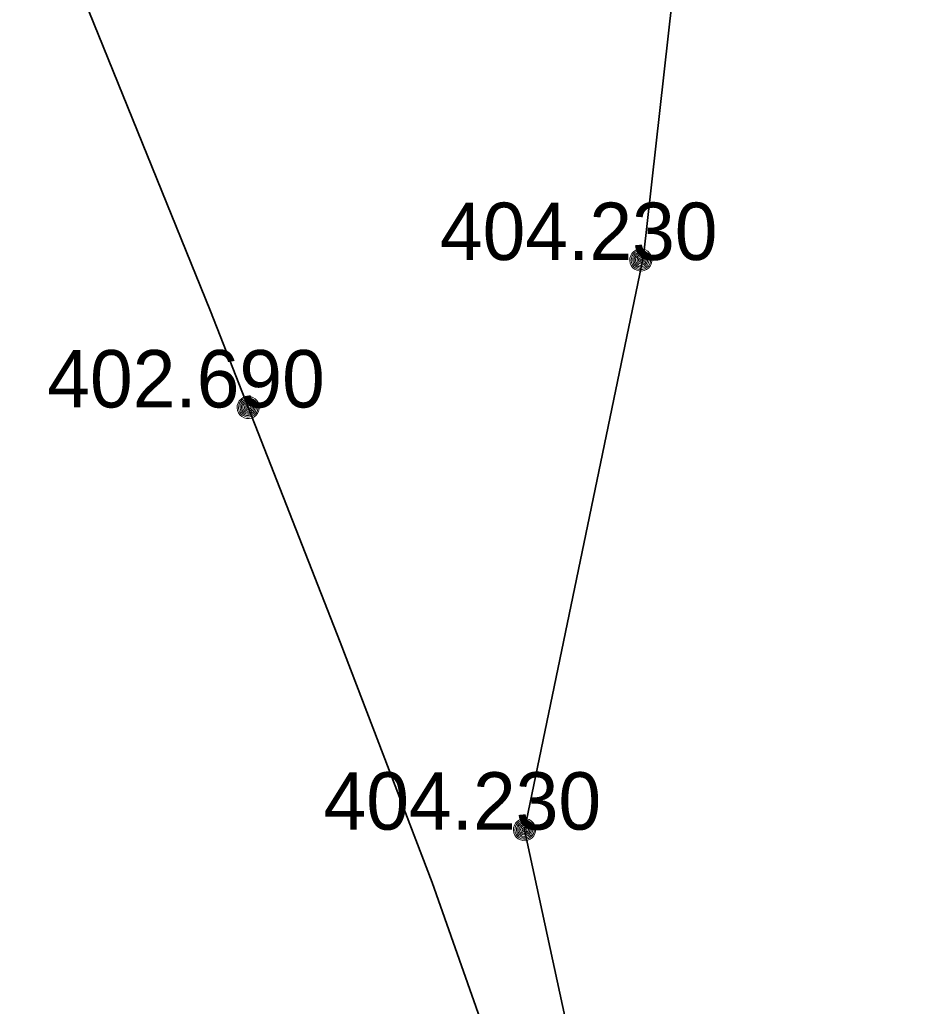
# Model space of a CAD drawing. Extents: x -873619 to -867639, y -1015082 to -1012326.
# Drawn here: x -867993.66 to -867974.61, y -1012778.89 to -1012758.26 of the extents above; entities that cross this region are included whole.
import ezdxf

# ---------------------------------------------------------------- set-up
doc = ezdxf.new("R2010")
doc.units = 0
doc.header["$LTSCALE"] = 0.44
doc.layers.add('1', color=7, linetype='Continuous', lineweight=13)
doc.layers.add('21', color=7, linetype='Continuous', lineweight=35)

msp = doc.modelspace()

# ---------------------------------------------------------------- linework, layer by layer
at = {"layer": '1', "lineweight": 35}
msp.add_lwpolyline([(-867974.611, -1012725.697), (-867976.949, -1012730.385), (-867980.624, -1012763.205), (-867983.112, -1012775.195), (-867978.719, -1012795.525), (-867979.823, -1012805.464), (-867997.768, -1012829.005), (-868011.042, -1012836.499), (-868058.95, -1012844.4), (-868077.43, -1012833.46), (-868085.171, -1012827.86)], dxfattribs=at)
at = {"layer": '1'}
for points in [[(-867980.449, -1012763.287), (-867980.455, -1012763.235), (-867980.472, -1012763.185), (-867980.501, -1012763.141), (-867980.538, -1012763.104), (-867980.583, -1012763.077), (-867980.633, -1012763.06), (-867980.686, -1012763.056), (-867980.738, -1012763.063), (-867980.787, -1012763.082), (-867980.83, -1012763.111), (-867980.866, -1012763.15), (-867980.892, -1012763.195), (-867980.908, -1012763.246), (-867980.911, -1012763.298), (-867980.903, -1012763.35), (-867980.883, -1012763.399), (-867980.852, -1012763.442), (-867980.813, -1012763.476), (-867980.767, -1012763.502), (-867980.716, -1012763.516), (-867980.663, -1012763.518), (-867980.612, -1012763.508), (-867980.564, -1012763.487), (-867980.521, -1012763.456), (-867980.487, -1012763.415), (-867980.463, -1012763.369), (-867980.451, -1012763.318)], [(-867980.479, -1012763.287), (-867980.485, -1012763.238), (-867980.502, -1012763.192), (-867980.53, -1012763.152), (-867980.567, -1012763.12), (-867980.611, -1012763.098), (-867980.659, -1012763.087), (-867980.708, -1012763.087), (-867980.755, -1012763.1), (-867980.798, -1012763.124), (-867980.834, -1012763.157), (-867980.861, -1012763.198), (-867980.877, -1012763.245), (-867980.881, -1012763.294), (-867980.874, -1012763.342), (-867980.855, -1012763.387), (-867980.825, -1012763.427), (-867980.787, -1012763.458), (-867980.743, -1012763.478), (-867980.695, -1012763.488), (-867980.646, -1012763.486), (-867980.599, -1012763.471), (-867980.556, -1012763.446), (-867980.522, -1012763.412), (-867980.496, -1012763.37), (-867980.482, -1012763.323)], [(-867980.509, -1012763.287), (-867980.515, -1012763.242), (-867980.532, -1012763.2), (-867980.56, -1012763.165), (-867980.596, -1012763.138), (-867980.638, -1012763.121), (-867980.683, -1012763.116), (-867980.728, -1012763.122), (-867980.769, -1012763.141), (-867980.804, -1012763.169), (-867980.831, -1012763.206), (-867980.847, -1012763.248), (-867980.851, -1012763.293), (-867980.844, -1012763.338), (-867980.825, -1012763.379), (-867980.796, -1012763.413), (-867980.759, -1012763.439), (-867980.716, -1012763.455), (-867980.671, -1012763.458), (-867980.626, -1012763.45), (-867980.586, -1012763.43), (-867980.552, -1012763.401), (-867980.526, -1012763.363), (-867980.512, -1012763.32)], [(-867980.539, -1012763.287), (-867980.544, -1012763.246), (-867980.562, -1012763.209), (-867980.589, -1012763.178), (-867980.624, -1012763.157), (-867980.664, -1012763.146), (-867980.705, -1012763.148), (-867980.744, -1012763.161), (-867980.778, -1012763.185), (-867980.803, -1012763.217), (-867980.818, -1012763.255), (-867980.821, -1012763.296), (-867980.813, -1012763.336), (-867980.793, -1012763.372), (-867980.764, -1012763.401), (-867980.727, -1012763.42), (-867980.687, -1012763.428), (-867980.646, -1012763.424), (-867980.608, -1012763.409), (-867980.576, -1012763.383), (-867980.553, -1012763.349), (-867980.54, -1012763.31)], [(-867980.569, -1012763.287), (-867980.574, -1012763.251), (-867980.592, -1012763.219), (-867980.618, -1012763.194), (-867980.652, -1012763.179), (-867980.688, -1012763.176), (-867980.723, -1012763.184), (-867980.754, -1012763.204), (-867980.777, -1012763.232), (-867980.79, -1012763.266), (-867980.79, -1012763.303), (-867980.779, -1012763.338), (-867980.758, -1012763.367), (-867980.728, -1012763.388), (-867980.693, -1012763.398), (-867980.656, -1012763.396), (-867980.622, -1012763.382), (-867980.595, -1012763.359), (-867980.576, -1012763.327), (-867980.569, -1012763.292)], [(-867980.599, -1012763.287), (-867980.604, -1012763.256), (-867980.621, -1012763.23), (-867980.647, -1012763.213), (-867980.677, -1012763.206), (-867980.708, -1012763.21), (-867980.735, -1012763.227), (-867980.753, -1012763.251), (-867980.761, -1012763.282), (-867980.757, -1012763.312), (-867980.742, -1012763.34), (-867980.718, -1012763.359), (-867980.688, -1012763.368), (-867980.657, -1012763.365), (-867980.629, -1012763.351), (-867980.609, -1012763.327), (-867980.599, -1012763.298)], [(-867980.629, -1012763.287), (-867980.634, -1012763.263), (-867980.651, -1012763.245), (-867980.674, -1012763.236), (-867980.698, -1012763.239), (-867980.719, -1012763.253), (-867980.73, -1012763.275), (-867980.73, -1012763.3), (-867980.718, -1012763.321), (-867980.698, -1012763.335), (-867980.673, -1012763.338), (-867980.65, -1012763.329), (-867980.634, -1012763.311)], [(-867980.659, -1012763.287), (-867980.664, -1012763.272), (-867980.679, -1012763.266), (-867980.694, -1012763.27), (-867980.701, -1012763.284), (-867980.697, -1012763.299), (-867980.684, -1012763.308), (-867980.669, -1012763.305), (-867980.659, -1012763.293)], [(-867988.656, -1012766.369), (-867988.662, -1012766.317), (-867988.679, -1012766.267), (-867988.708, -1012766.223), (-867988.745, -1012766.186), (-867988.79, -1012766.159), (-867988.84, -1012766.142), (-867988.893, -1012766.138), (-867988.945, -1012766.145), (-867988.994, -1012766.164), (-867989.037, -1012766.193), (-867989.073, -1012766.232), (-867989.099, -1012766.277), (-867989.115, -1012766.328), (-867989.118, -1012766.38), (-867989.11, -1012766.432), (-867989.09, -1012766.481), (-867989.059, -1012766.524), (-867989.02, -1012766.558), (-867988.974, -1012766.584), (-867988.923, -1012766.598), (-867988.87, -1012766.6), (-867988.819, -1012766.59), (-867988.771, -1012766.569), (-867988.728, -1012766.538), (-867988.694, -1012766.497), (-867988.67, -1012766.451), (-867988.657, -1012766.4)], [(-867988.686, -1012766.369), (-867988.692, -1012766.32), (-867988.709, -1012766.274), (-867988.737, -1012766.234), (-867988.774, -1012766.202), (-867988.818, -1012766.18), (-867988.866, -1012766.169), (-867988.915, -1012766.169), (-867988.962, -1012766.182), (-867989.005, -1012766.206), (-867989.041, -1012766.239), (-867989.068, -1012766.28), (-867989.084, -1012766.327), (-867989.088, -1012766.376), (-867989.081, -1012766.424), (-867989.062, -1012766.469), (-867989.032, -1012766.509), (-867988.994, -1012766.54), (-867988.95, -1012766.56), (-867988.902, -1012766.57), (-867988.853, -1012766.568), (-867988.806, -1012766.553), (-867988.763, -1012766.528), (-867988.728, -1012766.494), (-867988.703, -1012766.452), (-867988.689, -1012766.405)], [(-867988.716, -1012766.369), (-867988.722, -1012766.324), (-867988.739, -1012766.282), (-867988.767, -1012766.247), (-867988.803, -1012766.22), (-867988.845, -1012766.203), (-867988.89, -1012766.198), (-867988.934, -1012766.204), (-867988.976, -1012766.223), (-867989.011, -1012766.251), (-867989.038, -1012766.288), (-867989.054, -1012766.33), (-867989.058, -1012766.375), (-867989.051, -1012766.42), (-867989.032, -1012766.461), (-867989.003, -1012766.495), (-867988.966, -1012766.521), (-867988.923, -1012766.537), (-867988.878, -1012766.54), (-867988.833, -1012766.532), (-867988.793, -1012766.512), (-867988.759, -1012766.483), (-867988.733, -1012766.445), (-867988.719, -1012766.402)], [(-867988.746, -1012766.369), (-867988.75, -1012766.328), (-867988.769, -1012766.291), (-867988.796, -1012766.26), (-867988.831, -1012766.239), (-867988.871, -1012766.228), (-867988.912, -1012766.23), (-867988.951, -1012766.243), (-867988.985, -1012766.267), (-867989.01, -1012766.299), (-867989.025, -1012766.337), (-867989.027, -1012766.378), (-867989.02, -1012766.418), (-867989, -1012766.454), (-867988.971, -1012766.483), (-867988.934, -1012766.502), (-867988.894, -1012766.51), (-867988.853, -1012766.506), (-867988.815, -1012766.491), (-867988.782, -1012766.465), (-867988.76, -1012766.431), (-867988.747, -1012766.392)], [(-867988.776, -1012766.369), (-867988.781, -1012766.333), (-867988.799, -1012766.301), (-867988.825, -1012766.276), (-867988.858, -1012766.261), (-867988.895, -1012766.258), (-867988.929, -1012766.266), (-867988.961, -1012766.286), (-867988.983, -1012766.314), (-867988.997, -1012766.348), (-867988.997, -1012766.385), (-867988.986, -1012766.42), (-867988.965, -1012766.449), (-867988.934, -1012766.47), (-867988.9, -1012766.48), (-867988.863, -1012766.478), (-867988.829, -1012766.464), (-867988.802, -1012766.441), (-867988.782, -1012766.409), (-867988.776, -1012766.374)], [(-867988.806, -1012766.369), (-867988.811, -1012766.338), (-867988.828, -1012766.312), (-867988.853, -1012766.295), (-867988.884, -1012766.288), (-867988.915, -1012766.292), (-867988.942, -1012766.309), (-867988.96, -1012766.333), (-867988.968, -1012766.364), (-867988.964, -1012766.394), (-867988.949, -1012766.422), (-867988.924, -1012766.441), (-867988.895, -1012766.45), (-867988.864, -1012766.447), (-867988.836, -1012766.433), (-867988.816, -1012766.409), (-867988.806, -1012766.38)], [(-867988.836, -1012766.369), (-867988.841, -1012766.345), (-867988.858, -1012766.327), (-867988.88, -1012766.318), (-867988.905, -1012766.321), (-867988.926, -1012766.335), (-867988.937, -1012766.357), (-867988.937, -1012766.382), (-867988.924, -1012766.403), (-867988.905, -1012766.417), (-867988.88, -1012766.42), (-867988.857, -1012766.411), (-867988.841, -1012766.393)], [(-867988.866, -1012766.369), (-867988.871, -1012766.354), (-867988.886, -1012766.348), (-867988.901, -1012766.352), (-867988.907, -1012766.366), (-867988.904, -1012766.381), (-867988.891, -1012766.39), (-867988.875, -1012766.387), (-867988.866, -1012766.375)], [(-867982.88, -1012775.195), (-867982.887, -1012775.143), (-867982.904, -1012775.093), (-867982.933, -1012775.049), (-867982.97, -1012775.012), (-867983.015, -1012774.985), (-867983.065, -1012774.968), (-867983.118, -1012774.964), (-867983.169, -1012774.971), (-867983.218, -1012774.99), (-867983.262, -1012775.019), (-867983.298, -1012775.058), (-867983.324, -1012775.103), (-867983.34, -1012775.154), (-867983.343, -1012775.206), (-867983.335, -1012775.258), (-867983.315, -1012775.307), (-867983.284, -1012775.35), (-867983.245, -1012775.384), (-867983.199, -1012775.41), (-867983.147, -1012775.424), (-867983.095, -1012775.426), (-867983.044, -1012775.416), (-867982.995, -1012775.395), (-867982.953, -1012775.364), (-867982.919, -1012775.323), (-867982.895, -1012775.277), (-867982.882, -1012775.226)], [(-867982.911, -1012775.195), (-867982.917, -1012775.146), (-867982.934, -1012775.1), (-867982.962, -1012775.06), (-867982.999, -1012775.028), (-867983.043, -1012775.006), (-867983.091, -1012774.995), (-867983.14, -1012774.995), (-867983.186, -1012775.008), (-867983.23, -1012775.032), (-867983.266, -1012775.065), (-867983.293, -1012775.106), (-867983.309, -1012775.153), (-867983.313, -1012775.202), (-867983.306, -1012775.25), (-867983.287, -1012775.295), (-867983.257, -1012775.335), (-867983.218, -1012775.366), (-867983.174, -1012775.386), (-867983.127, -1012775.396), (-867983.078, -1012775.394), (-867983.031, -1012775.379), (-867982.988, -1012775.354), (-867982.953, -1012775.32), (-867982.928, -1012775.278), (-867982.914, -1012775.231)], [(-867982.941, -1012775.195), (-867982.946, -1012775.15), (-867982.963, -1012775.108), (-867982.992, -1012775.073), (-867983.027, -1012775.046), (-867983.07, -1012775.029), (-867983.115, -1012775.024), (-867983.159, -1012775.03), (-867983.201, -1012775.049), (-867983.235, -1012775.077), (-867983.262, -1012775.114), (-867983.279, -1012775.156), (-867983.282, -1012775.201), (-867983.276, -1012775.246), (-867983.257, -1012775.287), (-867983.228, -1012775.321), (-867983.191, -1012775.347), (-867983.147, -1012775.363), (-867983.103, -1012775.366), (-867983.058, -1012775.358), (-867983.017, -1012775.338), (-867982.983, -1012775.309), (-867982.958, -1012775.271), (-867982.944, -1012775.228)], [(-867982.971, -1012775.195), (-867982.975, -1012775.154), (-867982.994, -1012775.117), (-867983.021, -1012775.086), (-867983.056, -1012775.065), (-867983.096, -1012775.054), (-867983.137, -1012775.056), (-867983.176, -1012775.069), (-867983.21, -1012775.093), (-867983.235, -1012775.125), (-867983.25, -1012775.163), (-867983.252, -1012775.204), (-867983.245, -1012775.244), (-867983.225, -1012775.28), (-867983.196, -1012775.309), (-867983.159, -1012775.328), (-867983.119, -1012775.336), (-867983.078, -1012775.332), (-867983.039, -1012775.317), (-867983.007, -1012775.291), (-867982.985, -1012775.257), (-867982.972, -1012775.218)], [(-867983, -1012775.195), (-867983.005, -1012775.159), (-867983.024, -1012775.127), (-867983.049, -1012775.102), (-867983.083, -1012775.087), (-867983.12, -1012775.084), (-867983.154, -1012775.092), (-867983.186, -1012775.112), (-867983.208, -1012775.14), (-867983.222, -1012775.174), (-867983.222, -1012775.211), (-867983.211, -1012775.246), (-867983.19, -1012775.275), (-867983.159, -1012775.296), (-867983.125, -1012775.306), (-867983.088, -1012775.304), (-867983.054, -1012775.29), (-867983.027, -1012775.267), (-867983.007, -1012775.235), (-867983, -1012775.2)], [(-867983.031, -1012775.195), (-867983.036, -1012775.164), (-867983.053, -1012775.138), (-867983.078, -1012775.121), (-867983.108, -1012775.114), (-867983.14, -1012775.118), (-867983.167, -1012775.135), (-867983.184, -1012775.159), (-867983.193, -1012775.19), (-867983.189, -1012775.22), (-867983.174, -1012775.248), (-867983.149, -1012775.267), (-867983.12, -1012775.276), (-867983.088, -1012775.273), (-867983.061, -1012775.259), (-867983.041, -1012775.235), (-867983.031, -1012775.206)], [(-867983.061, -1012775.195), (-867983.066, -1012775.171), (-867983.083, -1012775.153), (-867983.105, -1012775.144), (-867983.13, -1012775.147), (-867983.151, -1012775.161), (-867983.162, -1012775.183), (-867983.162, -1012775.208), (-867983.149, -1012775.229), (-867983.13, -1012775.243), (-867983.105, -1012775.246), (-867983.081, -1012775.237), (-867983.066, -1012775.219)], [(-867983.091, -1012775.195), (-867983.096, -1012775.18), (-867983.11, -1012775.174), (-867983.125, -1012775.178), (-867983.132, -1012775.192), (-867983.129, -1012775.207), (-867983.115, -1012775.216), (-867983.1, -1012775.213), (-867983.091, -1012775.201)]]:
    msp.add_lwpolyline(points, close=True, dxfattribs=at)
at = {"layer": '21'}
msp.add_lwpolyline([(-867992.326, -1012757.823), (-867989.674, -1012764.355), (-867986.967, -1012771.277), (-867985.041, -1012776.301), (-867983.561, -1012780.516)], dxfattribs=at)

# ---------------------------------------------------------------- texts
at = {"layer": '1'}
for s, p in [('404.230 ', (-867984.88, -1012763.287)), ('402.690 ', (-867993.087, -1012766.369)), ('404.230 ', (-867987.312, -1012775.195))]:
    msp.add_text(s, height=1.2, dxfattribs=at).set_placement(p)

doc.saveas('drawing.dxf')
